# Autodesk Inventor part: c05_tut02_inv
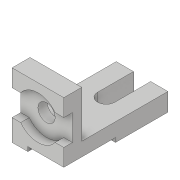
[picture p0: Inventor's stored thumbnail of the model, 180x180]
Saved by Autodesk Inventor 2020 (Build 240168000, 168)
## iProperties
Created: 2017-04
Part Number: c05_tut02_inv
Material: Generic
Document SubType Name: Modeling
Designer: CADCIM 00
Density: 1 g/cm^3
Appearance: Default
Author: CADCIM 00
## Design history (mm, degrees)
sketch "Sketch1"
  geometry: L1 (0, 0)-(0, 90); L2 (0, 90)-(25, 90); L3 (25, 90)-(25, 25); L4 (25, 25)-(145, 25); L5 (145, 25)-(145, 0); L6 (145, 0)-(0, 0)
  constraints: 12 end point, 6 perpendicular, 1 vertical
  dimensions: "d0" = 90 distance of L1.start L1.end; "d1" = 25 distance of L1.end L2.end; "d2" = 145 distance of L5.end L1.start
extrude "Extrusion1" new body sketch "Sketch1" stored distance "d3" = 72; taper "d4" = 0 deg
sketch "Sketch2"
  geometry: L1 (0, 0)-(0, 145) reference; L2 (0, 0)-(-6, 0); L3 (-6, 0)-(-6, 72); L4 (-6, 72)-(0, 72); L5 (0, 72)-(0, 0)
  constraints: 8 end point, 2 parallel, 1 horizontal, 1 perpendicular
  dimensions: "d5" = 72 distance between parallel lines of L4 L2; "d6" = 6 distance between parallel lines of L1 L3
extrude "Extrusion2" cut sketch "Sketch2" distance "d7" = 50; taper "d8" = 0 deg
sketch "Sketch3"
  geometry: L1 (0, 0)-(0, -65) reference; L2 (72, -65)-(72, 0) reference; L3 (72, -24)-(72, -60); L4 (0, -60)-(0, -24); L5 (0, -24)-(12, -24); L6 (60, -24)-(72, -24); L7 (72, -60)-(60, -60); L8 (12, -60)-(0, -60); L9 (72, -90)-(22, -90) reference; L10 (0, -90)-(22, -90) reference; A1 r 30 centre (36, -42) between (12, -60) and (60, -60); A2 r 30 centre (36, -42) between (60, -24) and (12, -24); 1 further point
  constraints: 12 end point, 5 parallel, 4 point on circle, 2 centre point, 2 collinear, 2 horizontal, 2 perpendicular, 2 point on line, 1 concentric
  dimensions: "d9" = 30 radius of A2; "d10" = 48 distance from line of L9 A1.centre; "d11" = 36 distance from line of L1 A1.centre; "d12" = 36 distance between parallel lines of L8 L5; "d13" = 30 distance between parallel lines of L10 L8
extrude "Extrusion3" cut sketch "Sketch3" distance "d14" = 12; taper "d15" = 0 deg
sketch "Sketch4"
  geometry: C1 r 12 at (36, -42); A1 r 30 centre (36, -42) between (60, -24) and (12, -24) reference; 1 further point
  constraints: 1 centre point, 1 concentric
  dimensions: "d16" = 24 diameter of C1
extrude "Extrusion4" cut sketch "Sketch4" stored distance "d17" = 12; taper "d18" = 0 deg
sketch "Sketch5"
  geometry: L1 (36, 119.693)-(36, 70); L2 (24, 119.693)-(24, 70); L3 (48, 70)-(48, 120); L4 (72, 120)-(0, 120) reference; L5 (24.004, 120)-(48, 120); L6 (72, 120)-(0, 120) reference; L7 (72, 120)-(72, 0) reference; A1 r 12 centre (36, 70) between (24, 70) and (48, 70); A2 r 12 centre (36, 119.693) between (24.004, 120) and (24, 119.693); 2 further points
  constraints: 10 end point, 4 point on circle, 3 tangent, 2 centre point, 2 point on line, 2 vertical, 1 collinear, 1 midpoint, 1 parallel
  dimensions: "d19" = 50 distance from line of L1.end L4; "d20" = 12 radius of A1; "d21" = 36 distance between parallel lines of L7 L1
extrude "Extrusion5" cut sketch "Sketch5" extent not by distance; stored distance "d22" = 12; taper "d23" = 0 deg
body "Solid1"
